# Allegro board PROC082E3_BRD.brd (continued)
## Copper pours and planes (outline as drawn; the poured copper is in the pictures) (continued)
VDD11_CSI_HUB3 on BOTTOM: 8.34,42.05 8.34,42.28 7.86,42.76 3.03,42.76 3.03,54.62 4.86,54.62 5.79,55.55 5.79,58.62 8.47,58.62 8.47,53.58 8.27,53.38 5.67,53.38 5.67,47.1 5.8,46.97 8.34,46.97 8.34,47 16.29,47 16.29,51.57 18.22,51.57 18.22,45.5 15.91,43.19 10.17,43.19 9.94,42.96 9.94,42.05
VDD11_CSI_HUB3 on L03_SIG1: 6.86,55.09 10.16,55.09 10.54,54.71 10.54,49.61 12.67,47.47 17.96,47.47 18.36,47.07 18.36,43.87 17.83,43.33 7.59,43.33 5.97,44.96 5.97,54.2
VDD11_CSI_HUB3 on L04_PWR1: 7.06,54.99 7.06,53.8 8.66,53.8 8.66,46.08 8.05,45.47 8.05,43.97 8.36,43.66 11.63,43.66 11.63,52.81 9.45,54.99
VDD11_FPD_HUB1 on BOTTOM (solid shape): 24.52,143.78 24.54,143.74 24.54,140.67 21.68,140.67 21.68,142.15 22.17,142.65 22.17,143.85 24.49,143.85
VDD11_FPD_HUB1 on L04_PWR1: 21.19,143.99 21.19,123.93 36.05,123.93 36.05,143.99
VDD11_FPD_HUB2 on BOTTOM (solid shape): 30.39,43.92 30.39,40.18 28.88,40.18 28.88,41.35 27.88,42.34 27.39,42.34 27.39,43.92
VDD11_FPD_HUB2 on L04_PWR1: 28.12,44.82 28.12,40.78 37.02,40.78 37.02,46 43.24,46 43.24,58.05 48.32,58.05 48.32,62.26 47.37,63.21 47.37,67.94 36.8,67.94 36.8,58.51 32.29,58.51 32.29,44.82
VDD11_FPD_HUB3 on BOTTOM: 14.95,42.2 13.56,42.2 13.56,43.99 14.22,44.65 17.35,44.65 17.35,43.51 15.42,43.51 14.95,43.04
VDD11_FPD_HUB3 on L04_PWR1: 11.35,65.37 11.35,43.33 18.7,43.33 18.7,44.41 21.01,46.71 21.01,62.1 17.96,65.15 16.54,65.15 16.54,63.73 14.72,63.73 12.76,65.7 11.68,65.7
VDD11_L_HUB1 on BOTTOM: 29.93,148.48 29.93,145.35 32.37,145.35 32.37,148.48
VDD11_L_HUB1 on L04_PWR1: 30.21,148.59 30.21,145.93 32.2,145.93 36.99,141.13 36.99,123.34 22.69,123.34 22.69,119.71 34.87,119.71 35.73,118.85 39.78,118.85 40.63,119.69 40.63,141.82 33.86,148.59
VDD11_L_HUB2 on BOTTOM (solid shape): 28.24,39.55 30.02,39.55 30.02,37.19 29.54,36.71 29.54,36.12 28.51,36.12 28.51,37.91 28.28,38.14 27.37,38.14 27.37,39.74 28.24,39.74
VDD11_L_HUB2 on L03_SIG1: 28.53,39.87 28.53,36.79 30.35,36.79 30.35,39.87
VDD11_L_HUB3 on BOTTOM: 20.8,42.43 18.82,42.43 18.82,46.02 20.19,46.02 20.19,44.45 20.58,44.07 20.8,44.07
VDD11_L_HUB3 on L04_PWR1: 4.55,59.08 8.26,59.08 8.26,68.47 19.67,68.47 21.77,66.37 21.77,47.4 19.89,45.52 19.02,45.52 18.77,45.26 18.77,42.95 19.3,42.42 24.71,42.42 25.78,43.48 25.78,72.42 4.55,72.42
VDD11_P0_HUB1 on BOTTOM: 28.92,152.1 28.92,150 32.7,150 32.7,152.1
VDD11_P0_HUB1 on L04_PWR1: 30,152.53 36.56,152.53 45.69,143.39 45.69,109.7 40.77,104.78 34.92,104.78 34.89,104.74 19.14,104.74 17.59,106.3 17.59,111.67 24.6,111.67 24.6,109.9 25.4,109.09 31.24,109.09 31.62,108.71 31.62,107.95 32.51,107.06 35.7,107.06 35.7,118.9 40.73,118.9 41.34,119.5 41.34,142.03 34.15,149.23 30,149.23
VDD11_P0_HUB2 on BOTTOM (solid shape): 30.52,48.87 28.78,48.87 28.78,50.11 28.53,50.11 28.53,50.53 28.28,50.78 27.44,50.78 27.44,52.42 30.52,52.42
VDD11_P0_HUB2 on TOP: 30.3,50.5 28.55,50.5 28.55,54.6 34.87,60.92 34.87,72.24 35.03,72.39 37.16,72.39 37.19,72.36 37.19,59.49 30.3,52.6
VDD11_P0_HUB3 on BOTTOM: 7.1,35.33 3.72,35.33 3.72,38.91 5.98,38.91 5.98,36.92 6.3,36.6 7.1,36.6
VDD11_P0_HUB3 on L04_PWR1: 4.06,35.29 5.97,35.29 5.97,44.32 8.32,46.67 8.32,53.17 6.44,53.17 6.44,52.47 5.9,51.94 4.06,51.94
VDD11_P1_HUB2 on TOP: 45.62,66.62 45.62,65.02 46.18,64.47 47.52,64.47 47.52,63.63 45.11,63.63 44.5,64.24 44.5,67.77 45.57,68.83 46.51,68.83 46.51,67.51
VDD11_P1_HUB3 on L04_PWR1: 5.6,52.57 4.06,52.57 4.06,58.67 8.66,58.67 8.66,68.23 15.88,68.23 15.88,64.6 14.84,64.6 12.81,66.63 11.46,66.63 10.81,65.98 10.81,55.45 5.89,55.45 5.89,54.11 5.6,53.82
VDD18_FPD_HUB1 on BOTTOM: 22.41,132.24 22.41,130.21 25.56,130.21 25.56,132.24
VDD18_FPD_HUB1 on L03_SIG1: 37.03,122 37.03,125.16 36.59,125.6 35.11,125.6 33.59,127.12 26.86,127.12 25.67,128.31 25.67,130.42 25.31,130.79 22.68,130.79 22.68,121.11 36.14,121.11
VDD18_FPD_HUB2 on TOP: 37.27,73.9 35.34,73.9 35.34,76.59 37.27,76.59
VDD18_FPD_HUB2 on L6_SIG2: 35.07,76.44 35.07,73.88 36.31,73.88 37.39,74.95 48.65,74.95 49.91,73.69 49.91,70.2 48.39,68.68 48.39,60.49 49.13,59.75 50.07,59.75 50.31,59.99 50.31,64.94 51.31,65.93 51.31,74.03 49.3,76.03 38.16,76.03 37.75,76.44
VDD18_FPD_HUB3 on TOP: 8.59,61.21 8.59,68.07 24.35,68.07 24.35,64.12 21.44,61.21
VDD18_FPD_HUB3 on L03_SIG1: 9.11,68.4 22.67,68.4 22.67,64.22 21.5,63.05 12.25,63.05 11.02,61.82 10.24,61.82 9.11,62.95
VDD_1V1_HUB1 on TOP: 43.08,107.44 43.81,107.44 43.81,108.43 44.27,108.89 44.68,108.89 44.68,109.47 43.84,109.47 43.54,109.78 43.54,111.51 42.95,111.51 42.95,108.41 43.08,108.28
VDD_1V1_HUB2 on TOP: 23.52,34.29 22.23,34.29 21.49,33.55 19.96,33.55 19.96,32.54 23.83,32.54 23.83,33.38 23.52,33.68
VDD_1V1_HUB3 on TOP: 12.95,35.61 9.4,35.61 9.4,34.75 11.4,34.75 12.5,33.66 13.26,33.66 13.26,34.54 12.95,34.85
VDD_3V3 on TOP: 39.37,97.69 39.37,94.64 35.92,94.64 35.92,97.69
VDD_3V3 on L04_PWR1: 13.92,80.39 13.92,76.29 25.72,76.29 38.99,89.56 38.99,95.25 35.76,95.25 35.76,93.42 22.73,80.39
(no net) on TOP: 67.08,80.87 67.08,79.71 70.16,79.71 70.16,80.87
(no net) on TOP: 13.98,171.39 13.98,168 14.92,168 14.92,171.39
(no net) on TOP: 63.91,125.46 63.91,123.88 64.64,123.88 64.64,125.46
(no net) on TOP: 64.81,61.48 64.81,58.36 67.9,58.36 67.9,59.41 66.24,59.41 65.76,59.89 65.76,61.48
(no net) on TOP: 10.21,171.39 10.21,170.19 13.27,170.19 13.27,171.39
(no net) on TOP: 13.27,147.1 13.27,145.9 8.38,145.9 8.38,147.1
(no net) on TOP: 71.53,125.12 72.69,125.12 72.69,122.28 73.05,121.92 73.84,121.92 73.84,119.76 72.95,118.87 70.94,118.87 70.94,121.92 71.53,122.5
(no net) on TOP: 63.91,167.53 63.91,166.04 64.64,166.04 64.64,167.53
(no net) on TOP: 67.06,159.05 67.06,156.11 68.3,156.11 68.3,159.05
(no net) on TOP: 65.18,80.87 65.18,77.98 68.3,77.98 68.3,79.07 66.45,79.07 66.09,79.43 66.09,80.87
(no net) on TOP: 10.35,119.91 10.35,118.9 16,118.9 16,120.84 13.47,120.84 12.54,119.91
(no net) on TOP: 7.39,167.35 7.39,164.73 11.46,164.73 11.46,167.35
(no net) on TOP: 67.03,101.07 67.03,102.16 70.13,102.16 70.13,99.31 69.19,99.31 69.19,100.53 68.66,101.07
(no net) on TOP: 13.27,169.2 13.27,168 8.38,168 8.38,169.2
(no net) on TOP: 10.21,105.1 10.21,103.9 13.27,103.9 13.27,105.1
(no net) on TOP: 67.98,64.68 67.49,64.19 63.79,64.19 63.79,71.03 66.07,71.03 67.98,69.11
(no net) on TOP: 67.06,119.94 67.06,116.99 68.3,116.99 68.3,119.94
(no net) on TOP: 65.51,107.42 65.51,104.75 66.55,104.75 66.55,107.42
(no net) on TOP: 64.12,87.88 67.34,87.88 68.01,87.21 68.01,83.25 67.85,83.09 64.12,83.09
(no net) on TOP: 71.53,164.24 72.69,164.24 72.69,161.39 73.05,161.04 73.84,161.04 73.84,158.88 72.95,157.99 70.94,157.99 70.94,161.04 71.53,161.62
(no net) on TOP: 13.98,105.09 13.98,101.71 14.92,101.71 14.92,105.09
(no net) on TOP: 7.39,101.06 7.39,98.45 11.46,98.45 11.46,101.06
(no net) on TOP: 68.31,45.07 67.92,44.68 64.12,44.68 64.12,51.36 66.04,51.36 66.37,51.69 67.59,51.69 68.31,50.97
(no net) on TOP: 67.08,100.38 67.08,97.43 68.3,97.43 68.3,100.38
(no net) on TOP: 10.21,149.29 10.21,148.09 13.27,148.09 13.27,149.29
(no net) on TOP: 13.98,149.29 13.98,145.91 14.92,145.91 14.92,149.29
(no net) on TOP: 10.21,127.19 10.21,126 13.27,126 13.27,127.19
(no net) on TOP: 65.39,81.55 64.91,81.55 64.32,80.96 64.32,77.95 62.71,77.95 62.04,78.63 62.04,80.73 61.48,81.29 61.48,82.53 61.58,82.64 65.39,82.64
(no net) on TOP: 13.27,125 13.27,123.81 8.43,123.81 8.43,125
(no net) on TOP: 67.06,139.5 67.06,136.53 68.3,136.53 68.3,139.5
(no net) on TOP: 10.35,142.01 10.35,141 16.05,141 16.05,142.94 13.47,142.94 12.54,142.01
(no net) on TOP: 66.7,61.34 66.7,60.12 70.08,60.12 70.08,61.34
(no net) on TOP: 13.98,127.19 13.98,123.81 14.92,123.81 14.92,127.19
(no net) on TOP: 67.03,120.62 67.03,121.72 70.13,121.72 70.13,118.87 69.19,118.87 69.19,120.09 68.66,120.62
(no net) on TOP: 7.39,123.16 7.39,120.55 11.46,120.55 11.46,123.16
(no net) on TOP: 10.35,164.11 10.35,163.09 16.05,163.09 16.05,165.04 13.47,165.04 12.54,164.11
(no net) on TOP: 10.38,97.81 10.38,96.8 15.25,96.8 15.25,99.05 13.78,99.05 12.54,97.81
(no net) on TOP: 67.03,140.18 67.03,141.27 70.13,141.27 70.13,138.43 69.19,138.43 69.19,139.65 68.66,140.18
(no net) on TOP: 71.53,144.68 72.69,144.68 72.69,141.83 73.05,141.48 73.79,141.48 73.79,139.27 72.95,138.43 70.94,138.43 70.94,141.48 71.53,142.06
(no net) on TOP: 65.51,150.14 65.51,147.57 66.55,147.57 66.55,150.14
(no net) on TOP: 65.51,170.66 65.51,168 66.55,168 66.55,170.66
(no net) on TOP: 65.51,128.5 65.51,125.83 66.55,125.83 66.55,128.5
(no net) on TOP: 7.39,145.25 7.39,142.65 11.46,142.65 11.46,145.25
(no net) on TOP: 13.27,102.9 13.27,101.71 8.43,101.71 8.43,102.9
(no net) on TOP: 71.53,105.56 72.69,105.56 72.69,102.72 73.05,102.36 73.76,102.36 73.76,100.13 72.95,99.31 70.94,99.31 70.94,102.36 71.53,102.95
(no net) on TOP: 65.06,62.52 63.99,61.45 63.99,58.33 61.94,58.33 61.71,58.56 61.71,61.66 61.15,62.21 61.15,63.46 61.25,63.56 65.06,63.56
(no net) on TOP: 63.91,104.09 63.91,102.64 64.64,102.64 64.64,104.09
(no net) on TOP: 67.03,159.74 67.03,160.83 70.13,160.83 70.13,157.99 69.19,157.99 69.19,159.21 68.66,159.74
(no net) on BOTTOM: 24.54,143.85 24.54,140.67 21.68,140.67 21.68,142.15 22.17,142.65 22.17,143.85
(no net) on BOTTOM: 65.56,99.95 65.56,98.32 66.29,98.32 66.29,99.95
(no net) on BOTTOM: 24.06,148.14 24.06,145.06 21.75,145.06 21.75,146.64 20.81,146.64 20.81,148.14
(no net) on BOTTOM: 27.39,46.77 27.39,48.23 30.42,48.23 30.42,44.55 28.68,44.55 28.68,46.32 28.23,46.77
(no net) on BOTTOM: 16.12,163.42 9.21,163.42 8.68,162.88 7.71,162.88 7.71,163.77 7.58,163.9 6.21,163.9 6.21,165.47 6.03,165.65 6.03,166.62 15.92,166.62 16.12,166.42
(no net) on BOTTOM: 8.12,136.52 7.79,136.19 6.77,136.19 6.77,137.13 6.72,137.18 6.26,137.18 6.19,137.25 6.19,138.24 7.56,138.24 7.69,138.37 7.69,138.99 9.09,138.99 9.34,139.24 11.8,139.24 11.93,139.11 11.93,136.52
(no net) on BOTTOM: 16.09,119.02 9.21,119.02 8.68,118.48 7.71,118.48 7.71,119.37 7.58,119.5 6.21,119.5 6.21,121.07 6.03,121.25 6.03,122.21 15.73,122.21 16.09,121.85
(no net) on BOTTOM: 67.31,158.19 67.31,157.33 70.46,157.33 70.46,158.19
(no net) on BOTTOM: 74.96,88.98 75.29,89.31 76.31,89.31 76.31,88.37 76.36,88.32 76.82,88.32 76.89,88.24 76.89,87.25 75.52,87.25 75.39,87.12 75.39,86.44 74.19,86.44 74.02,86.26 72.31,86.26 72.12,86.45 72.12,88.74 72.36,88.98
(no net) on BOTTOM: 27.39,43.92 30.39,43.92 30.39,40.18 28.88,40.18 28.88,41.35 27.88,42.34 27.39,42.34
(no net) on BOTTOM: 66.14,27.46 73.38,27.46 74.27,28.35 75.37,28.35 75.37,27.59 75.49,27.46 76.87,27.46 76.87,25.88 77.04,25.71 77.04,24.74 73.72,24.74 71.38,22.4 67.47,22.4 65.77,24.1 65.77,27.09
(no net) on BOTTOM: 65.56,118.9 65.56,117.47 66.29,117.47 66.29,118.9
(no net) on BOTTOM: 67.31,118.57 67.31,117.7 70.46,117.7 70.46,118.57
(no net) on BOTTOM: 67.31,138.63 67.31,137.77 70.46,137.77 70.46,138.63
(no net) on BOTTOM: 74.91,31.32 75.29,31.7 76.31,31.7 76.31,30.76 76.36,30.71 76.82,30.71 76.89,30.63 76.89,29.64 75.52,29.64 75.39,29.52 75.39,28.85 73.89,28.85 73.76,28.73 71.15,28.73 71.15,31.32
(no net) on BOTTOM: 65.56,138.94 65.56,137.44 66.29,137.44 66.29,138.94
(no net) on BOTTOM: 65.89,66.24 73.87,66.24 74.4,66.78 75.37,66.78 75.37,65.89 75.49,65.76 76.87,65.76 76.87,64.19 77.04,64.01 77.04,63.04 65.89,63.04
(no net) on BOTTOM: 65.56,158.55 65.56,157 66.29,157 66.29,158.55
(no net) on BOTTOM: 15.84,103.54 16.84,102.55 16.84,99.57 15.57,98.3 10.72,98.3 9.31,96.89 7.66,96.89 7.66,97.65 7.53,97.77 6.13,97.77 6.13,98.66 6.03,98.76 6.03,100.27 9.31,103.54
(no net) on BOTTOM: 16.07,139.95 9.21,139.95 8.68,139.41 7.71,139.41 7.71,140.3 7.58,140.43 6.21,140.43 6.21,142 6.03,142.18 6.03,145.12 6.21,145.3 15.23,145.3 16.07,144.45
(no net) on BOTTOM: 1.02,1.02 1.02,189.48 82.14,189.48 82.14,1.02 ; 25 cut-outs
(no net) on BOTTOM: 65.46,46.8 66.89,46.8 67.69,46 70.55,46 71.35,46.8 73.87,46.8 74.4,47.33 75.37,47.33 75.37,46.44 75.49,46.31 76.87,46.31 76.87,44.74 77.04,44.56 77.04,43.6 73.72,43.6 71.38,41.26 65.59,41.26 65.28,41.56 65.28,46.62
(no net) on BOTTOM: 67.31,99.52 67.31,98.65 70.46,98.65 70.46,99.52
(no net) on BOTTOM: 74.96,69.67 75.29,70 76.31,70 76.31,69.06 76.36,69.01 76.82,69.01 76.89,68.94 76.89,67.95 75.52,67.95 75.39,67.82 75.39,67.13 73.94,67.13 73.76,66.96 71.28,66.96 71.15,67.08 71.15,69.67
(no net) on BOTTOM: 27.37,38.14 27.37,39.74 30.02,39.74 30.02,36.12 28.51,36.12 28.51,37.91 28.28,38.14
(no net) on BOTTOM: 8.12,93.92 7.79,93.59 6.77,93.59 6.77,94.53 6.72,94.58 6.26,94.58 6.19,94.66 6.19,95.65 7.56,95.65 7.69,95.78 7.69,96.42 8.97,96.42 9.19,96.64 10.04,96.64 10.04,94.27 9.69,93.92
(no net) on BOTTOM: 8.12,115.59 7.79,115.26 6.77,115.26 6.77,116.2 6.72,116.25 6.26,116.25 6.19,116.32 6.19,117.31 7.56,117.31 7.69,117.44 7.69,118.08 8.99,118.08 9.21,118.31 11.13,118.31 11.16,118.27 11.16,115.59
(no net) on BOTTOM: 26.35,41.72 26.35,40.4 28.1,40.4 28.1,41.69 27.93,41.87 26.5,41.87
(no net) on BOTTOM: 65.89,85.55 73.87,85.55 74.4,86.08 75.37,86.08 75.37,85.19 75.49,85.07 76.87,85.07 76.87,83.49 77.04,83.31 77.04,82.35 65.89,82.35
(no net) on BOTTOM: 10.49,41.03 12.43,41.03 12.43,42.78 10.49,42.78
(no net) on BOTTOM: 27.44,52.42 30.52,52.42 30.52,48.74 28.53,48.74 28.53,50.53 28.28,50.78 27.44,50.78
(no net) on BOTTOM: 74.9,50.16 75.29,50.56 76.31,50.56 76.31,49.62 76.36,49.57 76.82,49.57 76.89,49.49 76.89,48.5 75.52,48.5 75.39,48.37 75.39,47.7 73.9,47.7 73.71,47.51 71.48,47.51 71.48,51.41 73,51.41 73.25,51.16 73.25,50.55 73.63,50.16
(no net) on BOTTOM: 8.12,159.99 7.79,159.66 6.77,159.66 6.77,160.6 6.72,160.65 6.26,160.65 6.19,160.72 6.19,161.71 7.56,161.71 7.69,161.84 7.69,162.43 9.2,162.43 9.47,162.7 11.8,162.7 11.93,162.58 11.93,159.99
(no net) on BOTTOM: 69.39,158.83 69.39,160.89 65.89,160.89 65.89,160.89 65.75,160.89 65.75,164.2 65.94,164.39 67.54,164.39 67.84,164.09 73.87,164.09 74.4,164.62 75.37,164.62 75.37,163.73 75.49,163.6 76.87,163.6 76.87,162.03 77.04,161.85 77.04,160.89 74.7,160.89 72.97,159.16 72.97,158.83
(no net) on BOTTOM: 26.35,37.78 26.35,35.65 28.1,35.65 28.1,37.78
C_CAM6_RIN1_P on TOP: 70.84,57.72 70.84,56.82 71.98,56.82 71.98,57.72
C_CAM8_RIN3_P on TOP: 70.83,18.61 70.83,17.7 72.01,17.7 72.01,18.61
C_CAM9_RIN0_P on TOP: 10.34,105.62 10.34,106.5 11.48,106.5 11.48,105.62
LM25085A_ISEN on BOTTOM: 59.1,1.22 59.1,6.43 58.93,6.6 52.2,6.6 51.82,6.22 51.82,6.22 51.82,4.45 50.26,4.45 50.26,3.38 50.04,3.15 50.04,1.27 50.29,1.02 58.89,1.02
LM25085A_ISEN on L6_SIG2: 60.56,1.02 60.56,15.62 50.91,15.62 50.91,1.02
V_CAM5 on TOP (solid shape): 68.01,87.21 68.01,83.25 67.85,83.09 64.12,83.09 64.12,86.1 64.39,86.1 64.39,87.88 67.34,87.88
V_CAM5 on BOTTOM (solid shape): 75.3,85 76.77,85 76.77,83.97 76.87,83.97 76.87,83.49 77.04,83.31 77.04,82.35 65.89,82.35 65.89,85.55 73.87,85.55 73.95,85.63 74.28,85.63 74.45,85.8 75.3,85.8
V_CAM6 on TOP (solid shape): 67.98,69.11 67.98,64.68 67.49,64.19 65.69,64.19 65.69,64.2 63.79,64.2 63.79,68.97 63.97,68.97 63.97,70.75 63.79,70.75 63.79,71.03 66.07,71.03
V_CAM6 on BOTTOM (solid shape): 75.3,65.69 76.77,65.69 76.77,64.66 76.87,64.66 76.87,64.19 77.04,64.01 77.04,63.04 65.89,63.04 65.89,66.24 73.87,66.24 73.95,66.32 74.02,66.32 74.2,66.5 75.3,66.5
V_CAM7 on TOP (solid shape): 68.31,50.97 68.31,45.07 67.92,44.68 64.12,44.68 64.12,51.36 64.35,51.36 64.35,51.35 66.13,51.35 66.13,51.44 66.37,51.69 67.59,51.69
V_CAM7 on BOTTOM (solid shape): 75.3,46.25 76.77,46.25 76.77,45.22 76.87,45.22 76.87,44.74 77.04,44.56 77.04,43.6 73.72,43.6 71.38,41.26 65.59,41.26 65.28,41.56 65.28,46.62 65.46,46.8 66.89,46.8 67.69,46 70.55,46 70.78,46.23 72.77,46.23 72.77,46.17 72.79,46.12 72.81,46.07 72.83,46.02 72.87,45.97 72.91,45.93 72.95,45.9 73,45.88 73.06,45.86 73.11,45.85 73.17,45.85 73.22,45.85 73.28,45.87 73.33,45.89 73.37,45.92 73.42,45.95 73.45,45.99 73.48,46.04 73.51,46.09 73.52,46.15 73.53,46.2 73.53,46.26 73.52,46.31 73.51,46.36 73.48,46.41 73.45,46.46 73.42,46.5 73.37,46.54 73.33,46.57 73.28,46.59 73.22,46.6 73.17,46.61 73.11,46.61 73.06,46.6 73,46.58 72.95,46.55 72.91,46.52 72.87,46.48 72.83,46.44 72.81,46.39 72.79,46.34 72.77,46.28 72.77,46.23 70.78,46.23 71.35,46.8 73.87,46.8 73.95,46.87 73.97,46.87 74.17,47.07 75.3,47.07
V_CAM8 on BOTTOM (solid shape): 75.3,27.39 76.77,27.39 76.77,26.36 76.87,26.36 76.87,25.88 77.04,25.71 77.04,24.74 73.72,24.74 71.38,22.4 67.47,22.4 65.77,24.1 65.77,26.7 72.82,26.7 72.83,26.64 72.84,26.59 72.86,26.53 72.88,26.48 72.92,26.44 72.96,26.4 73,26.37 73.05,26.34 73.11,26.33 73.16,26.32 73.22,26.31 73.27,26.32 73.33,26.33 73.38,26.36 73.42,26.39 73.47,26.42 73.5,26.46 73.54,26.51 73.56,26.56 73.58,26.61 73.58,26.67 73.58,26.72 73.58,26.78 73.56,26.83 73.54,26.88 73.5,26.93 73.47,26.97 73.42,27.01 73.38,27.03 73.33,27.06 73.27,27.07 73.22,27.08 73.16,27.07 73.11,27.06 73.05,27.05 73,27.02 72.96,26.99 72.92,26.95 72.88,26.91 72.86,26.86 72.84,26.81 72.83,26.75 72.82,26.7 65.77,26.7 65.77,27.09 66.14,27.46 73.38,27.46 74.02,28.09 74.02,28.09 74.15,28.22 75.3,28.22
V_CAM8 on TOP: 63.45,30.99 63.45,28.83 65.81,26.47 65.81,25.04 68.38,25.04 68.38,30.99
V_CAM9 on TOP (solid shape): 15.25,96.81 13.44,96.81 13.44,96.8 10.38,96.8 10.38,97.81 12.54,97.81 13.78,99.05 15.25,99.05
V_CAM9 on BOTTOM (solid shape): 16.84,102.55 16.84,99.57 15.57,98.3 10.72,98.3 9.7,97.27 8.92,97.27 8.7,97.05 7.78,97.05 7.78,97.9 6.31,97.9 6.31,98.93 6.03,98.93 6.03,100.27 9.31,103.54 15.84,103.54
V_CAM10 on TOP (solid shape): 16,118.9 15.22,118.9 15.22,118.91 13.44,118.91 13.44,118.9 10.35,118.9 10.35,119.91 12.54,119.91 13.47,120.84 16,120.84
V_CAM10 on BOTTOM (solid shape): 16.09,121.85 16.09,119.02 9.21,119.02 9.13,118.94 8.95,118.94 8.73,118.72 7.78,118.72 7.78,119.57 6.31,119.57 6.31,120.6 6.21,120.6 6.21,121.07 6.03,121.25 6.03,122.21 15.73,122.21
V_CAM11 on TOP (solid shape): 16.05,141 15.22,141 15.22,141.01 13.44,141.01 13.44,141 10.35,141 10.35,142.01 12.54,142.01 13.47,142.94 16.05,142.94
V_CAM11 on BOTTOM (solid shape): 16.07,144.45 16.07,139.95 9.21,139.95 9.13,139.87 9.08,139.87 8.83,139.62 7.78,139.62 7.78,140.5 6.31,140.5 6.31,141.53 6.21,141.53 6.21,142 6.03,142.18 6.03,144.87 6.09,144.96 6.2,144.95 6.58,144.92 6.8,145.25 6.8,145.3 15.23,145.3
V_CAM12 on TOP (solid shape): 16.05,163.09 15.22,163.09 15.22,163.1 13.44,163.1 13.44,163.09 10.35,163.09 10.35,164.1 12.1,164.1 12.1,164.11 12.54,164.11 13.47,165.04 16.05,165.04
V_CAM12 on BOTTOM (solid shape): 16.12,166.42 16.12,163.42 9.21,163.42 8.86,163.07 7.78,163.07 7.78,163.97 6.31,163.97 6.31,165 6.21,165 6.21,165.47 6.03,165.65 6.03,166.62 15.92,166.62
V_RAD/CAM1 on BOTTOM (solid shape): 67.84,164.09 73.87,164.09 73.95,164.16 74.25,164.16 74.41,164.31 75.3,164.31 75.3,163.53 76.77,163.53 76.77,162.5 76.87,162.5 76.87,162.03 77.04,161.85 77.04,160.89 74.7,160.89 72.97,159.16 72.97,158.83 69.39,158.83 69.39,160.89 69.32,160.89 69.32,160.91 66.28,160.91 66.04,161.15 66.04,164.39 67.54,164.39
V_RAD/CAM1 on TOP: 65.38,167.18 66.55,167.18 66.55,166.29 67.08,165.76 70.92,165.76 70.92,161.85 65.38,161.85
V_RAD/CAM1_CON1 on BOTTOM: 68.68,159.16 68.68,160.27 66.01,160.27 65.41,160.88 65.41,175.64 63.96,177.09 58.75,177.09 57.47,175.81 57.47,171.2 58.88,171.2 58.88,174.32 59.79,175.23 63.09,175.23 64.01,174.32 64.01,160.6 65.46,159.16
V_RAD/CAM1_CON3 on TOP: 59.49,170.13 59.97,170.61 64.69,170.61 64.69,168.14 63.86,168.14 63.86,168.39 63.07,169.19 59.89,169.19 59.49,169.6
V_RAD/CAM2 on TOP: 65.36,146.76 67.25,146.76 67.25,146.23 71,146.23 71,141.91 65.36,141.91
V_RAD/CAM2 on BOTTOM: 69.42,139.27 69.42,141.25 65.89,141.25 65.89,141.26 65.81,141.26 65.81,144.81 69.41,144.81 69.76,144.45 74.12,144.45 74.47,144.81 75.37,144.81 75.37,144.1 75.49,143.97 76.87,143.97 76.87,142.39 77.04,142.22 77.04,141.25 75.13,141.25 73.15,139.27
V_RAD/CAM2_CON1 on BOTTOM: 68.58,139.57 68.58,140.69 65.99,140.69 65.3,141.38 65.3,152.88 63.37,154.81 59.41,154.81 57.38,152.78 57.38,149.61 58.95,149.61 58.95,151.92 60.58,153.54 63.02,153.54 63.53,153.03 63.53,140.36 64.31,139.57
V_RAD/CAM2_CON3 on TOP: 59.49,148.54 59.87,148.92 61.75,148.92 62.97,150.14 64.62,150.14 64.62,147.6 59.89,147.6 59.49,148.01
V_RAD/CAM3 on TOP: 65.39,125.53 67.06,125.53 67.28,125.76 67.28,126.62 71.03,126.62 71.03,122.22 65.39,122.22
V_RAD/CAM3 on BOTTOM: 69.42,119.35 69.42,121.24 68.82,121.24 68.82,121.74 65.75,121.74 65.75,124.88 66.04,125.17 69.81,125.17 70.57,124.41 73.87,124.41 74.25,124.79 75.37,124.79 75.37,124.06 75.49,123.93 76.87,123.93 76.87,122.35 77.04,122.18 77.04,121.21 73.84,121.21 73.03,120.4 73.03,119.35
V_RAD/CAM3_CON1 on TOP: 64.8,126.07 64.8,131.88 63.3,133.38 59.49,133.38 57.49,131.38 57.49,128.03 58.79,128.03 58.79,130.9 60.01,132.12 62.7,132.12 63.6,131.23 63.6,126.07
V_RAD/CAM3_CON3 on BOTTOM: 68.57,120.55 68.01,121.1 63.57,121.1 60.82,123.85 60.82,126.92 60.41,127.32 59.85,127.32 59.35,126.82 59.35,121.96 61.79,119.52 68.57,119.52
V_RAD/CAM4 on TOP: 65.46,103.96 66.4,103.96 67.28,104.85 67.28,107.09 70.94,107.09 70.94,102.74 65.46,102.74
V_RAD/CAM4 on BOTTOM: 69.39,100.15 69.39,101.67 67.55,101.67 66.71,102.5 66.71,105.27 67.56,106.12 69.62,106.12 70.88,104.87 73.87,104.87 74.4,105.4 75.37,105.4 75.37,104.51 75.49,104.38 76.87,104.38 76.87,102.81 77.04,102.63 77.04,101.67 74.46,101.67 72.95,100.15
V_RAD/CAM4_CON1 on TOP: 64.8,104.74 64.8,110.29 63.3,111.79 59.49,111.79 57.49,109.79 57.49,106.44 58.79,106.44 58.79,109.31 60.01,110.53 62.7,110.53 63.49,109.74 63.49,104.74
V_RAD/CAM4_CON3 on BOTTOM: 68.61,100.48 68.61,101.57 65.68,101.57 65.68,104.48 64.47,105.7 59.79,105.7 59.49,105.4 59.49,104.83 59.95,104.37 62.75,104.37 63.55,103.57 63.55,101.04 64.11,100.48
VIO_CLK_OSC on L6_SIG2: 7.43,76.5 7.43,72.35 22.05,72.35 22.05,82 12.93,82
VMAIN on TOP: 57.45,16.01 27.88,16.01 27.88,1.03 52.88,1.03 52.9,1.02 57.45,1.02
VMAIN on BOTTOM: 48.77,4.44 47.7,4.44 46.61,5.54 46.61,6.68 46.71,6.78 47.54,6.78 47.64,6.87 47.64,8.55 46.68,9.51 38.33,9.51 36.63,7.8 31.63,7.8 31.63,17.78 25.47,17.78 25.47,1.02 48.96,1.02 48.96,4.25
VMAIN on L03_SIG1: 27.92,1.03 60.53,1.03 60.53,14.22 27.92,14.22
VMAIN on L6_SIG2: 26.32,1.02 47.94,1.02 47.94,13.28 26.32,13.28
VREG_3V3 on TOP: 24.87,30.25 24.87,29.46 25.27,29.06 25.63,29.06 25.63,25.55 20.7,20.62 13.72,20.62 11.73,22.61 11.73,27.38 11.99,27.64 12.19,27.64 12.5,27.94 12.5,31.39 14.3,31.39 14.3,30.81 14.99,30.12 14.99,28.24 15.01,28.22 17.17,28.22 17.73,28.78 22.25,28.78 23.06,29.59 23.06,30.25 ; 1 cut-out
VREG_3V3 on TOP: 37.59,104.57 42.47,104.57 43.05,105.16 44.88,105.16 44.88,104.42 45.72,103.58 45.72,101.63 45.69,101.6 38.1,101.6 37.59,102.11
VREG_3V3 on BOTTOM: 32.41,27.97 32.41,36.75 32.16,37.01 30.73,37.01 30.18,36.45 30.18,35.43 29.97,35.23 25.68,35.23 25.68,33.88 24.92,33.12 20.37,33.12 19.46,32.21 19.46,25.58 19.33,25.45 18.26,25.45 17.58,24.77 17.58,23.93 17.63,23.88 17.98,23.88 18.11,23.75 18.11,22.89 19.02,22.89 19.25,22.66 19.25,22.63 24.51,22.63 24.51,27.43 25.04,27.97
VREG_3V3 on L04_PWR1: 38.73,104.14 39.62,103.25 39.62,101.35 39.3,101.02 32.94,101.02 31.62,99.69 24.38,99.69 14.61,89.92 5.84,89.92 5.46,89.53 5.46,72.9 3.56,70.99 3.56,34.98 5.25,33.28 21.68,33.28 23.62,31.34 23.62,23.88 22.86,23.11 19.94,23.11 17.78,25.27 5.59,25.27 1.02,29.84 1.02,91.31 2.79,93.09 10.16,93.09 15.49,98.42 15.49,99.95 19.68,104.14
VREG_3V3 on L6_SIG2: 20.24,26.87 20.24,23.34 22.94,23.34 22.94,26.87
VREG_3V3_SW on BOTTOM: 27.37,18.45 27.37,23.55 36.86,23.55 36.86,22.2 37.55,21.5 38.38,21.5 38.38,20.7 37.2,20.7 35.99,19.49 35.99,18.45
N23276823 on TOP (solid shape): 70.13,157.99 69.19,157.99 69.19,159.21 68.66,159.74 67.03,159.74 67.03,160.83 70.13,160.83
N23276832 on TOP (solid shape): 72.69,161.39 73.05,161.04 73.77,161.04 73.77,159.21 73.84,159.21 73.84,158.88 72.95,157.99 70.94,157.99 70.94,161.04 71.53,161.62 71.53,164.24 72.69,164.24
N23276850 on TOP: 68.96,157.33 68.96,156.01 72.03,156.01 72.03,157.33
N23276958 on TOP (solid shape): 68.3,156.11 67.06,156.11 67.06,159.05 68.3,159.05
N23280059 on TOP (solid shape): 64.64,166.04 63.91,166.04 63.91,167.53 64.64,167.53
N23280068 on BOTTOM (solid shape): 66.29,157 65.56,157 65.56,158.55 66.29,158.55
N23280320 on TOP (solid shape): 66.55,168 65.51,168 65.51,170.66 66.55,170.66
N23280326 on BOTTOM (solid shape): 70.46,157.33 67.31,157.33 67.31,158.19 70.46,158.19
N23290514 on TOP (solid shape): 70.13,138.43 69.19,138.43 69.19,139.65 68.66,140.18 67.03,140.18 67.03,141.27 70.13,141.27
N23290520 on TOP (solid shape): 72.69,141.83 73.05,141.48 73.77,141.48 73.77,139.65 73.79,139.65 73.79,139.27 72.95,138.43 70.94,138.43 70.94,141.48 71.53,142.06 71.53,144.68 72.69,144.68
N23290544 on TOP: 68.88,137.74 68.88,136.45 72.03,136.45 72.03,137.74
N23290557 on TOP (solid shape): 68.3,136.53 67.06,136.53 67.06,139.5 68.3,139.5
N23290898 on BOTTOM (solid shape): 66.29,137.44 65.56,137.44 65.56,138.94 66.29,138.94
N23290929 on TOP (solid shape): 66.55,147.57 65.51,147.57 65.51,150.14 66.55,150.14
N23290931 on BOTTOM (solid shape): 70.46,137.77 67.31,137.77 67.31,138.63 70.46,138.63
N23296098 on TOP (solid shape): 70.13,118.87 69.19,118.87 69.19,120.09 68.66,120.62 67.03,120.62 67.03,121.72 70.13,121.72
N23296110 on TOP (solid shape): 72.69,122.28 73.05,121.92 73.77,121.92 73.77,120.09 73.84,120.09 73.84,119.76 72.95,118.87 70.94,118.87 70.94,121.92 71.53,122.5 71.53,125.12 72.69,125.12
N23296124 on TOP: 68.86,118.21 68.86,116.87 72.03,116.87 72.03,118.21
N23296133 on TOP (solid shape): 68.3,116.99 67.06,116.99 67.06,119.94 68.3,119.94
N23296478 on TOP (solid shape): 64.64,123.88 63.91,123.88 63.91,125.44 64.64,125.44
N23296488 on BOTTOM (solid shape): 66.29,117.47 65.56,117.47 65.56,118.89 66.29,118.89
N23296513 on BOTTOM (solid shape): 70.46,117.7 67.31,117.7 67.31,118.57 70.46,118.57
N23296515 on TOP (solid shape): 66.55,125.83 65.51,125.83 65.51,128.5 66.55,128.5
N23301401 on TOP (solid shape): 70.13,99.31 69.19,99.31 69.19,100.53 68.66,101.07 67.03,101.07 67.03,102.16 70.13,102.16
N23301413 on TOP (solid shape): 72.69,102.72 73.05,102.36 73.76,102.36 73.76,100.13 72.95,99.31 70.94,99.31 70.94,102.36 71.53,102.95 71.53,105.56 72.69,105.56
N23301427 on TOP: 68.86,98.65 68.86,97.43 72.03,97.43 72.03,98.65
N23301436 on TOP (solid shape): 68.3,97.43 67.08,97.43 67.08,100.38 68.3,100.38
N23301766 on TOP (solid shape): 64.64,102.64 63.91,102.64 63.91,104.09 64.64,104.09
N23301784 on BOTTOM (solid shape): 66.29,98.32 65.56,98.32 65.56,99.85 66.29,99.85
N23301809 on BOTTOM (solid shape): 70.46,98.65 67.31,98.65 67.31,99.52 70.46,99.52
N23301811 on TOP (solid shape): 66.55,105.01 66.28,104.75 65.51,104.75 65.51,107.42 66.55,107.42
N23304842 on TOP (solid shape): 66.09,79.43 66.45,79.07 68.3,79.07 68.3,77.98 65.18,77.98 65.18,80.87 66.09,80.87
N23304854 on TOP (solid shape): 63.49,82.46 65.39,82.46 65.39,81.55 64.91,81.55 64.32,80.96 64.32,77.95 62.71,77.95 62.04,78.63 62.04,80.73 61.48,81.29 61.48,82.53 61.53,82.58 63.27,82.58 63.27,82.64 63.49,82.64
N23304868 on TOP: 70.8,80.93 70.8,77.7 72.07,77.7 72.07,80.93
N23304877 on TOP (solid shape): 70.16,79.71 67.08,79.71 67.08,80.87 70.16,80.87
N23306297 on TOP (solid shape): 65.76,59.89 66.24,59.41 67.9,59.41 67.9,58.36 64.81,58.36 64.81,61.37 64.92,61.48 65.76,61.48
N23306309 on TOP (solid shape): 65.06,62.52 63.99,61.45 63.99,58.33 61.94,58.33 61.71,58.56 61.71,61.66 61.15,62.21 61.15,63.46 61.2,63.51 62.94,63.51 62.94,63.56 65.06,63.56
N23306323 on TOP: 70.8,61.33 70.8,58.14 72.07,58.14 72.07,61.33
N23306330 on TOP (solid shape): 70.08,60.12 66.7,60.12 66.7,61.34 70.08,61.34
N23308323 on TOP: 72.39,40.59 72.39,45.36 73.41,45.36 73.41,40.59
N23308335 on TOP: 71.63,49.4 70.46,50.57 68.99,50.57 68.99,49.56 69.29,49.56 70.26,48.59 70.26,42.61 71.63,42.61
N23308349 on TOP: 68.61,39.92 68.61,38.87 72.03,38.87 72.03,39.92
N23308356 on TOP: 68.61,41.81 68.61,40.61 71.7,40.61 71.7,41.81
N23309323 on TOP: 72.39,21.08 72.39,25.81 73.36,25.81 73.36,21.08
N23309335 on TOP: 71.63,29.84 70.46,31.01 68.99,31.01 68.99,30 69.29,30 70.13,29.16 70.13,22.99 71.63,22.99
N23309349 on TOP: 68.61,20.45 68.61,19.3 72.01,19.3 72.01,20.45
N23309356 on TOP: 68.61,22.23 68.61,21.08 71.7,21.08 71.7,22.23
N23545074 on TOP (solid shape): 13.27,101.71 8.43,101.71 8.43,102.9 13.27,102.9
N23545086 on TOP (solid shape): 11.46,98.45 7.39,98.45 7.39,101.06 11.46,101.06
N23545100 on TOP (solid shape): 13.27,103.9 10.21,103.9 10.21,105.1 13.27,105.1
N23545106 on TOP (solid shape): 14.92,101.71 13.98,101.71 13.98,105.09 14.92,105.09
N23545339 on TOP (solid shape): 13.27,123.81 8.43,123.81 8.43,125 13.27,125
N23545354 on TOP (solid shape): 11.46,120.55 7.39,120.55 7.39,123.16 11.46,123.16
N23545368 on TOP (solid shape): 13.27,126 10.21,126 10.21,127.19 13.27,127.19
N23545374 on TOP (solid shape): 14.92,123.81 13.98,123.81 13.98,127.19 14.92,127.19
N23546296 on TOP (solid shape): 13.27,145.9 8.38,145.9 8.38,147.1 13.27,147.1
N23546308 on TOP (solid shape): 11.46,142.65 7.39,142.65 7.39,145.25 11.46,145.25
N23546322 on TOP (solid shape): 13.27,148.09 10.21,148.09 10.21,149.29 13.27,149.29
N23546328 on TOP (solid shape): 14.92,145.91 13.98,145.91 13.98,149.29 14.92,149.29
N23546802 on TOP (solid shape): 13.27,168 8.38,168 8.38,169.2 13.27,169.2
N23546814 on TOP (solid shape): 11.46,164.73 7.39,164.73 7.39,167.35 11.46,167.35
N23546828 on TOP (solid shape): 13.27,170.19 10.21,170.19 10.21,171.39 13.27,171.39
N23546834 on TOP (solid shape): 14.92,168 13.98,168 13.98,171.39 14.92,171.39
N24608149 on TOP: 69.02,13.07 69.02,1.03 58.67,1.03 58.67,14.17 67.91,14.17
N24763516 on BOTTOM: 68.45,13.72 49.36,13.72 49.36,10.06 49.53,9.89 53.38,9.89 55.28,7.98 55.28,7.34 55.39,7.23 59.24,7.23 59.74,6.74 59.74,1.02 68.45,1.02

Small or netless copper shapes (teardrops, artwork), in the pictures only: 199 on TOP, 225 on BOTTOM, 37 on L03_SIG1, 93 on L6_SIG2

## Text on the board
Ref Des/Assembly Bottom: BOTTOM J7x FUSION2 SERIAL CAPTURE BOARD REV.E3
Ref Des/Silkscreen Bottom: A | DGND | CAM9 | CAM10 | CAM11 | CAM12 | EXT_12V | CSI-TX | RADAR3 | RADAR4 | RADAR1 | RADAR2 | CAM2 | CAM4 | CAM1 | CAM8 | CAM3 | CAM5 | CAM6 | CAM7 | CSI-TX FPD | PCB #:PROC082 | PCB REV:E3 | SERIAL CAPTURE BRD | J7X FUSION2 | ASSY | SL# | J7EXPA01EVM | OPN#
User.Comments: A | B | C | D | E | 1 | 2 | 3 | 4 | 5 | 36 | 35 | 14 | 12 | 10 | 8 | 6 | 13 | 11 | 9 | 7 | F | G | H | J | K | L | M | N | P | card ejected | fully inserted | ejection | 119 | 59 | 60 | 120 | 40 | 39 | BOARD NAME: | PR0C082E3 | REV: E3 | DATE: 11/03/2022 | DESCRIPTION: | SHEET | OF | 15 | PROC082 | SCALE: 1 | CR_ETHERNET_1 | CR_EFUSE1_4 | CR_EFUSE1_2 | CR_EFUSE1_3 | CR_RF_PWR_4_1 | CR_2_2 | CR_2_3 | CR_2_4 | CR_PC_1 | CR_912_3 | CR_PC_2 | CR_912_2 | CR_PC_3 | CR_912_1 | CR_EFUSE1_1 | CR_RADARIP_4 | CR_RADARIP_3 | CR_RADARIP_1 | CR_FC_1 | CR_R_1 | CR_R_2 | CR_CIS_EFUSE_3 | CR_CIS_EFUSE_2 | TEXAS INSTRUMENTS | CR_HD1_1 | CR_RF_PWR_3_4 | CR_RF_PWR_3_3 | CR_RF_PWR_3_2 | CR_RC_1 | CR_RC_2 | CR_LC1_4 | CR_LC1_1 | CR_R_3 | CR_RF_PWR_3_1 | CR_3_1 | CR_RLC_DES_1 | CR_RLC_DES_2 | CR_RLC_DES_3 | CR_LC_1 | CR_LC3_1 | CR_2_1 | CR_LC_2 | CR_RF_PWR_4 | CR_RF_PWR_1 | CR_RF_PWR_3 | CR_FL_2 | CR_LC_3 | CR_4_2 | CR_4_1 | CR_R1_1 | CR_TPS25_6 | CR_PWR_1 | CR_R_4 | CR_LC3_2 | CR_PWR_4 | CR_PWR_3 | CR_TEST_2 | CR_CIS_EFUSE_1 | CR_DES_1 | CR_PWRC_1 | CR_PWRC_2 | CR_RADARIP_2 | CR_PWRC_4 | CR_PWR_2 | CR_1_9 | CR_LC1_3 | BASY CP CARD REV E3
Ref Des/Assembly Top: TOP J7x FUSION2 SERIAL CAPTURE BOARD REV.E3
Ref Des/Silkscreen Top: A | NOT FCC APPROVED FOR RESALE | CSI2 EXP AUX | FOR EVALUATION ONLY; | CSI1 EXP
PAGE_OUTLINE: LAYOUT BY | REVIEWED BY | APPROVED BY | SIGNATURES | AMB | SS | ZA | DATE | 110121 | SIZE | SCALE: | D | NONE | SHEET 1 OF 15 | PROC082 | Rev | E3 | TEXAS INSTRUMENTS | PROC082E3
DISPLAY_BOTTOM: 15. | ALL THE IMPEDANCE SHALL BE MATCHED AS PER IMPEDANCE TABLE WITH +/-10% TOLERANCE. | ALL UNCONNECTED VIA'S SHALL BE SUPPRESSED IN INTERNAL LAYERS. | VIA HOLES THAT HAVE MASK OPEN SHALL BE FILLED WITH NON CONDUCTIVE INK AND CAP PLATED,
User.5: CARD EJECTED | CARD LOCK | CARD OVER STROCK | D | C | B | A | BASY CP CARD REV E3
User.6: CARD EJECTED | CARD LOCK | CARD OVER STROCK | D | C | B | A | BASY CP CARD REV E3
User.7: 33 | 64 | 65 | 32 | 2 | 9 | 96 | 10 | 16 | 5 | 4 | 3 | 128 | 97 | 14 | 7 | 8 | 45 | 31 | 56 | 29 | 46 | 30 | 60 | 15 | 28 | 13 | 59 | 119 | 36 | 120 | 48 | 57 | 58 | 74 | 75 | 35 | 24 | 12 | 19 | 6 | 25 | 17 | 37 | 49 | 23 | 40 | 39 | 11 | $ | % | @ | # | R601 | R604 | R723 | C475 | R717 | J49 | C455 | C488 | R691 | R620 | Y7 | C549 | C456 | R727 | C487 | U138 | C615 | U144 | R818 | U120 | R594 | C480 | C449 | R872 | R577 | U141 | C510 | U158 | C656 | C482 | R676 | U119 | R893 | U104 | C548 | R897 | R605 | C664 | U115 | R637 | U164 | R896 | C680 | FL42 | R687 | C545 | R698 | R895 | R688 | R690 | U118 | C695 | R766 | R785 | R894 | C627 | C663 | R639 | U113 | C544 | C512 | C606 | C611 | C741 | U157 | C655 | C612 | U117 | U121 | C515 | C489 | R608 | R759 | R638 | C511 | C712 | R658 | U106 | U116 | C543 | R853 | R859 | R812 | R643 | U112 | C474 | C479 | R599 | R784 | R682 | C579 | R905 | C693 | R904 | U165 | R850 | R855 | R858 | R865 | R846 | R852 | C704 | C469 | C473 | C686 | R907 | C685 | FL41 | R683 | U163 | R906 | C668 | C682 | R752 | R882 | R890 | FB2 | FB3 | C494 | C496 | C498 | C684 | C681 | C688 | C484 | J46 | R795 | R797 | R799 | R856 | C594 | R910 | C597 | R909 | U160 | R842 | R848 | R830 | C698 | C481 | C486 | C493 | C495 | C497 | R825 | C691 | C697 | R841 | R854 | C642 | R582 | C675 | D48 | U155 | TP92 | C450 | C725 | R794 | U166 | TP126 | R837 | FL46 | R839 | J47 | FL47 | R891 | B1 | U162 | C752 | C747 | R721 | U124 | R720 | R702 | C739 | C717 | TP127 | C743 | C578 | TP85 | R902 | U128 | R692 | C532 | C535 | C541 | FL8 | C540 | C546 | U152 | C630 | R733 | Q13 | C538 | C533 | C534 | J53 | U126 | C753 | C542 | C547 | R669 | R670 | R672 | R673 | C569 | R915 | U127 | U130 | U135 | U140 | U143 | U146 | TP82 | C458 | R609 | R642 | C568 | R648 | C696 | C740 | TP83 | C463 | R635 | C690 | C744 | R699 | C604 | C610 | C623 | C625 | C621 | C614 | C558 | C583 | C585 | C590 | C592 | C596 | C599 | FL45 | C506 | R743 | R745 | R755 | R765 | R776 | C565 | C555 | C557 | U110 | U145 | R920 | R697 | R919 | U150 | R739 | R740 | R728 | R732 | U142 | D45 | C564 | R215 | C570 | U139 | U134 | U153 | U123 | TP88 | TP84 | TP86 | TP87 | TP99 | R718 | TP100 | R208 | TP89 | TP101 | C577 | C761 | TP94 | TP95 | C504 | TP96 | C559 | C620 | C609 | C622 | C624 | C626 | C628 | C613 | R791 | C636 | C603 | C598 | C595 | C556 | TP97 | R742 | R744 | R749 | R754 | R761 | R764 | R771 | R774 | R778 | R782 | C749 | R696 | R700 | C638 | R712 | R719 | R879 | C643 | R928 | R810 | FB7 | C651 | C639 | C647 | C551 | C644 | FB6 | R913 | U156 | U167 | C602 | R703 | R655 | R659 | R634 | R636 | C582 | R737 | R722 | J52 | U129 | R916 | C619 | C731 | C748 | FB9 | Q14 | C576 | C573 | R657 | R918 | C601 | C618 | C654 | C648 | C446 | C629 | U107 | C649 | C653 | C758 | C645 | C472 | C600 | C575 | R793 | J48 | U147 | C591 | FB5 | U137 | C587 | U151 | R779 | FB4 | C617 | C755 | C574 | U171 | C521 | C616 | U168 | U161 | C593 | C608 | C607 | C734 | C751 | C746 | C502 | C707 | U108 | C509 | U36 | U149 | U172 | U148 | R661 | C765 | R660 | C763 | R602 | C713 | C729 | C728 | C710 | C706 | C723 | C735 | C736 | C703 | C719 | C700 | C718 | C694 | C714 | C745 | C699 | R627 | R817 | R626 | R934 | R816 | R625 | R815 | R814 | R813 | R819 | FL40 | C637 | C764 | R652 | C514 | R929 | R580 | R932 | D47 | R713 | R729 | C457 | R735 | R734 | C742 | C662 | R783 | C661 | C451 | R590 | C683 | C689 | C738 | C737 | C721 | R621 | R822 | R849 | C447 | R667 | R668 | U174 | R930 | R598 | R603 | R589 | U105 | C452 | C453 | C490 | R711 | R586 | R619 | R618 | R581 | R617 | R585 | R647 | R616 | R662 | C492 | R674 | R631 | U177 | R646 | R675 | R671 | R689 | R630 | R645 | R644 | C491 | R588 | C454 | R587 | R572 | C665 | R805 | C660 | U136 | R804 | R640 | R656 | R650 | R677 | R685 | R686 | R747 | R751 | R767 | R770 | R887 | R860 | C448 | R760 | R851 | R597 | C485 | R803 | C471 | C768 | R809 | R808 | C513 | R756 | R758 | U114 | C666 | R892 | C483 | R666 | R681 | C715 | R753 | FL39 | R806 | R665 | C769 | R847 | R807 | R762 | R664 | R871 | R663 | R680 | R861 | R888 | C517 | R787 | R796 | R843 | R595 | R679 | R757 | C516 | R781 | R800 | R802 | C466 | R873 | R801 | R607 | C464 | R780 | C677 | R833 | R870 | C467 | R832 | R869 | C465 | C468 | R606 | R844 | C462 | R684 | R649 | C461 | C672 | R868 | R840 | R867 | C671 | R866 | R829 | R835 | R828 | C705 | R834 | R862 | R775 | C670 | R827 | R826 | C669 | R836 | R678 | R748 | R600 | R831 | R824 | C499 | C505 | R823 | Y9 | C650 | C667 | TP103 | C501 | C500 | J51 | C711 | C478 | C687 | R629 | C477 | R628 | C476 | R857 | R864 | R624 | R863 | R821 | C632 | R820 | C646 | C631 | C658 | Q15 | C757 | C657 | C659 | C756 | C553 | C552 | C722 | C692 | C720 | R838 | C674 | R884 | R883 | C673 | R889 | C727 | R706 | C732 | R708 | C679 | R886 | R885 | C676 | R707 | C586 | R705 | R845 | C726 | C716 | C702 | C701 | U175 | R710 | R899 | C526 | R714 | R811 | C525 | R898 | C531 | U125 | R726 | C528 | C580 | R725 | C527 | R716 | R724 | FL43 | R596 | C589 | C635 | C539 | C524 | C537 | R579 | C588 | C523 | C536 | Y8 | C530 | R578 | C529 | R731 | R730 | R612 | FL44 | C724 | U176 | TP81 | R614 | FL38 | R613 | C563 | U111 | R653 | R633 | C470 | R903 | R695 | R591 | C507 | R901 | R217 | R693 | R750 | R763 | R772 | R651 | C571 | C169 | R900 | C566 | C508 | C550 | R623 | R694 | R622 | C640 | C168 | U109 | C581 | U170 | C567 | TP98 | R881 | R788 | R880 | R738 | R773 | TP102 | R736 | C678 | R715 | R878 | C708 | FB8 | C730 | C561 | U159 | C584 | C634 | C641 | C560 | U122 | C633 | C554 | C562 | R790 | R789 | R709 | R741 | U154 | C652 | R917 | R632 | R593 | R592 | R584 | R877 | R876 | R914 | U133 | R769 | R921 | R777 | C459 | R875 | C572 | R576 | R641 | R654 | D44 | R575 | R583 | U169 | R874 | R574 | C460 | C759 | U132 | R573 | U100 | R792 | C709 | C733 | R931 | C522 | C754 | C750 | R746 | R908 | C520 | R768 | J50 | C519 | D46 | C518 | C605 | C503 | U103 | U102 | U101 | U131 | PROC079 | 21 | OF | SECONDARY-SILKSCREEN | SHEET | DESCRIPTION: | DATE: 07/06/2019 | REV: E2 | J7X COMMON PROCESSOR BRD | BOARD NAME: | SCALE: 1 | MICRO SD | PCIe M.2 | DSI FPC | CSI2 EXP | CSI2 EXP AUX | NOT FCC APPROVED FOR RESALE | FOR EVALUATION ONLY; | EVM EXPANSION | TEST AUTOMATION | TEXAS INSTRUMENTS
User.8: 33 | 64 | 65 | 32 | 5 | 4 | 8 | 2 | 9 | 96 | 10 | 3 | 16 | 128 | 97 | 14 | 7 | 45 | 31 | 56 | 29 | 46 | 30 | 60 | 28 | 13 | 59 | 119 | 36 | 120 | 48 | 49 | 57 | 58 | 74 | 75 | 35 | 24 | 12 | 19 | 6 | 25 | 17 | 37 | 23 | 40 | 39 | 11 | $ | % | @ | # | PROC079 | 21 | OF | SECONDARY-SILKSCREEN | SHEET | DESCRIPTION: | DATE: 07/06/2019 | REV: E2 | J7X COMMON PROCESSOR BRD | BOARD NAME: | SCALE: 1 | MICRO SD | PCIe M.2 | DSI FPC | CSI2 EXP | CSI2 EXP AUX | NOT FCC APPROVED FOR RESALE | FOR EVALUATION ONLY; | EVM EXPANSION | TEST AUTOMATION | TEXAS INSTRUMENTS
User.9: 0.875 [22.23]
User.22: GROUND-PLANE-05 | 16
User.30: GROUND PLANE-02 | 08
User.33: POWER PLANE-01 | 07
User.35: GROUND PLANE-01
User.38: 06 | 03 | 04 | 02 | 05 | STRIPLINE | COPLANAR MICROSTRIP | MICROSTRIP | EDGE COUPLED MICROSTRIP | L3,L6 | L1,L8 | L1 | 17.5 | 4.0 | 3.5 | 6.0 | 5.1 | NA | 10.0 | 6.5 | 11 | 12 | 50 | 100 | L2/L4,L5/L7 | L3 | L2,L7
User.45: FIGURE | SIZE | 8.0 | 32.0 | 40.0 | 48.0 | 56.0 | 60.0 | 62.0 | 74.0 | 126.0 | 166.0 | DRILL CHART: TOP to BOTTOM | ALL UNITS ARE IN MILS | TOLERANCE | +3.0/-3.0 | +2.0/-2.0 | PLATED | NON-PLATED | QTY | 2713 | 16 | 5 | 7 | 8 | 20 | 2 | 32 | 6
